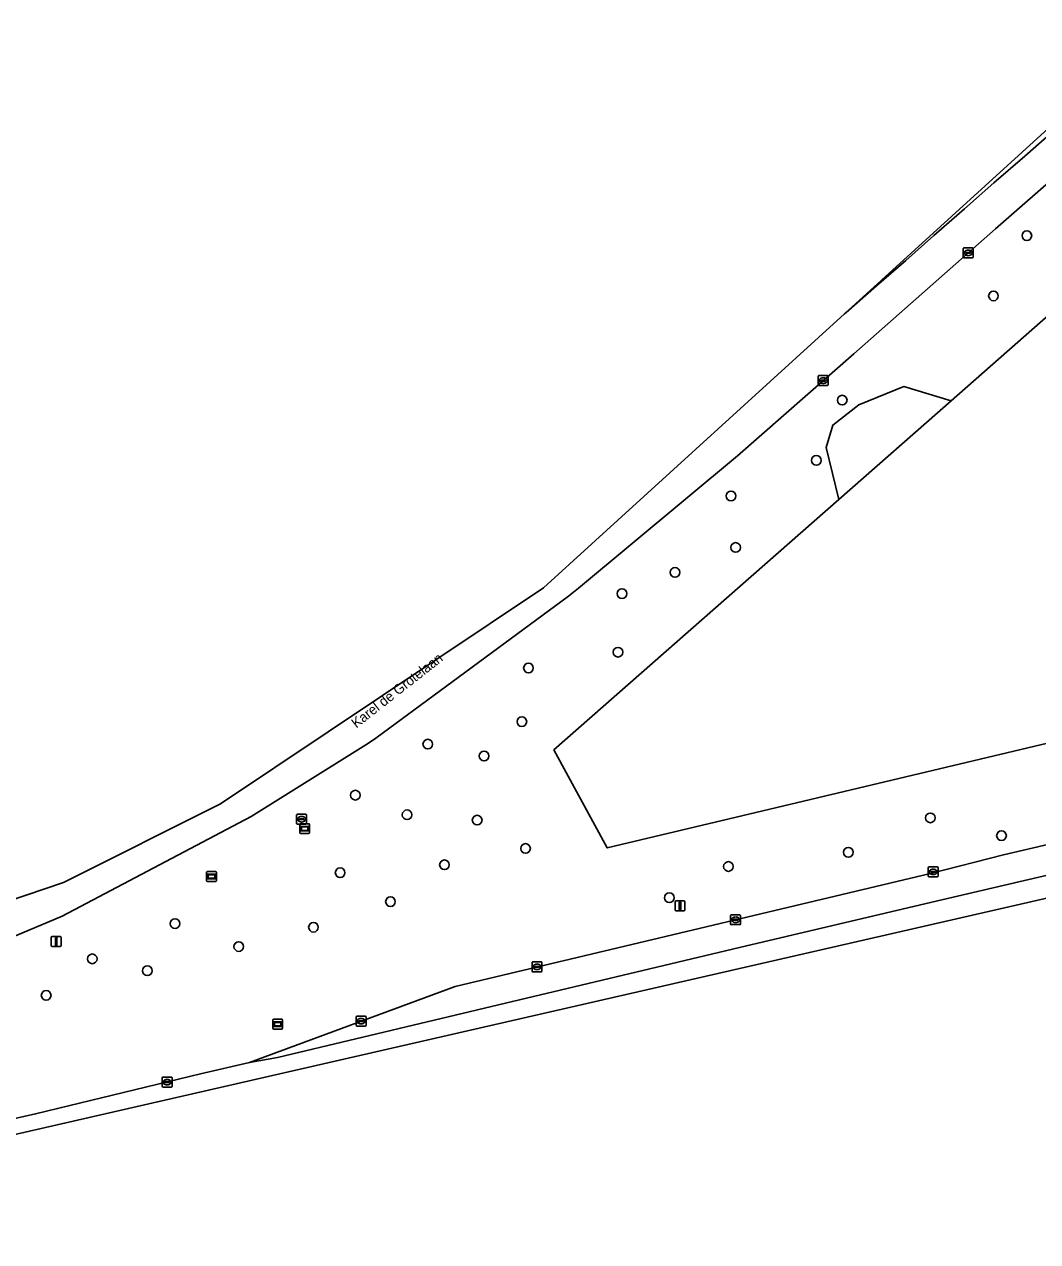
# Model space of a CAD drawing. Extents: x 158031 to 159244, y 380104 to 381214.
# Drawn here: x 158174 to 158276.2, y 380889.1 to 381011.9 of the extents above; entities that cross this region are included whole.
import ezdxf

# ---------------------------------------------------------------- set-up
doc = ezdxf.new("R2010")
doc.units = 0
for name, color, linetype in [('IMGEO_Afsluitpaal', 7, 'Continuous'), ('IMGEO_Berm_groen', 7, 'Continuous'), ('IMGEO_Boom', 7, 'Continuous'), ('IMGEO_Brandkraan', 7, 'Continuous'), ('IMGEO_Groenvoorziening', 7, 'Continuous'), ('IMGEO_Hek', 7, 'Continuous'), ('IMGEO_Kolk', 7, 'Continuous'), ('IMGEO_Lichtmast', 7, 'Continuous'), ('IMGEO_Openbare_ruimte_label', 7, 'Continuous'), ('IMGEO_Reclamebord', 7, 'Continuous'), ('IMGEO_Rijbaan_regionaal_gesloten', 7, 'Continuous'), ('IMGEO_Verklikker', 7, 'Continuous'), ('IMGEO_Wegwijzer', 7, 'Continuous')]:
    doc.layers.add(name, color=color, linetype=linetype)

msp = doc.modelspace()

# ---------------------------------------------------------------- linework, layer by layer
at = {"layer": 'IMGEO_Afsluitpaal'}
for p, q in [((158176.68, 380918.97), (158176.68, 380919.77)), ((158176.68, 380919.77), (158176.68, 380918.97)), ((158176.78, 380919.87), (158177.57, 380919.87)), ((158177.57, 380919.87), (158176.78, 380919.87)), ((158177.67, 380919.77), (158177.67, 380918.97)), ((158177.67, 380918.97), (158177.67, 380919.77)), ((158177.57, 380918.87), (158176.78, 380918.87)), ((158176.78, 380918.87), (158177.57, 380918.87))]:
    msp.add_line(p, q, dxfattribs=at)
msp.add_lwpolyline([(158177.1, 380919.74), (158177.25, 380919.74), (158177.25, 380918.99), (158177.1, 380918.99), (158177.1, 380919.74)], dxfattribs=at)
for centre, start, end in [((158176.78, 380919.77), 90, 180), ((158176.78, 380919.77), 90, 180), ((158177.57, 380919.77), 0, 90), ((158177.57, 380919.77), 360, 90), ((158176.78, 380918.97), 180, 270), ((158176.78, 380918.97), 180, 270), ((158177.57, 380918.97), 270, 0), ((158177.57, 380918.97), 270, 0)]:
    msp.add_arc(centre, 0.1, start, end, dxfattribs=at)
at = {"layer": 'IMGEO_Berm_groen'}
for points in [[(158278.95, 380997.38), (158271.98, 380991.29), (158257.69, 380978.69), (158245.96, 380968.39), (158229.89, 380955.02), (158228.88, 380954.2), (158209.44, 380939.88), (158208.7, 380939.39), (158196.86, 380931.99), (158177.79, 380921.93), (158156.82, 380913.1)], [(158282.76, 380940.68), (158232.8, 380928.81), (158227.42, 380938.7), (158256.18, 380963.98), (158254.89, 380969.21), (158255.55, 380971.48), (158258.19, 380973.54), (158262.74, 380975.37), (158267.5, 380973.93), (158290.8, 380994.41)], [(158153.95, 380897.19), (158175.11, 380901.96), (158191.76, 380905.99), (158196.68, 380907.16), (158217.44, 380914.82), (158265.44, 380926.24), (158272.8, 380928.1), (158289.52, 380932.01)]]:
    msp.add_lwpolyline(points, dxfattribs=at)
msp.add_lwpolyline([(158302.5, 380971.41), (158305.03, 380972.27), (158300.07, 380986.49), (158296.29, 380985.17), (158290.8, 380994.41), (158267.5, 380973.93), (158256.18, 380963.98), (158227.42, 380938.7), (158232.8, 380928.81), (158282.76, 380940.68), (158298.66, 380944.46), (158309.2, 380946.97)], close=True, dxfattribs=at)
at = {"layer": 'IMGEO_Boom'}
for centre in [(158275.15, 380990.6), (158271.78, 380984.52), (158256.51, 380974), (158253.9, 380967.92), (158245.29, 380964.33), (158245.76, 380959.13), (158239.64, 380956.61), (158234.29, 380954.47), (158233.89, 380948.56), (158224.85, 380946.96), (158224.18, 380941.55), (158214.69, 380939.28), (158220.37, 380938.08), (158207.38, 380934.13), (158212.6, 380932.15), (158219.67, 380931.61), (158265.41, 380931.84), (158272.59, 380930.05), (158224.55, 380928.75), (158257.13, 380928.36), (158205.84, 380926.3), (158216.37, 380927.1), (158245.03, 380926.93), (158239.07, 380923.78), (158210.92, 380923.39), (158189.18, 380921.17), (158203.15, 380920.8), (158195.61, 380918.85), (158180.82, 380917.61), (158186.38, 380916.41), (158176.17, 380913.92)]:
    msp.add_circle(centre, 0.489, dxfattribs=at)
at = {"layer": 'IMGEO_Brandkraan'}
for p, q in [((158201.45, 380931.27), (158201.45, 380932.13)), ((158201.52, 380932.2), (158202.38, 380932.2)), ((158201.71, 380931.69), (158201.71, 380931.71)), ((158201.75, 380931.74), (158202.15, 380931.74)), ((158202.15, 380931.66), (158201.75, 380931.66)), ((158201.94, 380931.98), (158201.96, 380931.98)), ((158202.19, 380931.71), (158202.19, 380931.69)), ((158202.45, 380932.13), (158202.45, 380931.27)), ((158202.38, 380931.2), (158201.52, 380931.2)), ((158201.96, 380931.42), (158201.93, 380931.42))]:
    msp.add_line(p, q, dxfattribs=at)
for points in [[(158201.45, 380931.27), (158201.45, 380932.13)], [(158201.52, 380932.2), (158202.38, 380932.2)], [(158202.45, 380932.13), (158202.45, 380931.27)], [(158202.38, 380931.2), (158201.52, 380931.2)]]:
    msp.add_lwpolyline(points, dxfattribs=at)
for centre, radius, start, end in [((158201.53, 380932.12), 0.0765, 91.552, 178.448), ((158201.53, 380932.12), 0.0765, 91.552, 178.448), ((158201.75, 380931.7), 0.0403, 85.8775, 175.7526), ((158201.74, 380931.69), 0.0366, 178.938, 274.7102), ((158202.15, 380931.7), 0.0386, 1.7309, 96.639), ((158202.15, 380931.7), 0.043, 264.8664, 352.4533), ((158202.37, 380932.12), 0.0765, 1.552, 88.448), ((158202.37, 380932.12), 0.0765, 1.552, 88.448), ((158201.53, 380931.28), 0.0765, 181.552, 268.448), ((158201.53, 380931.28), 0.0765, 181.552, 268.448), ((158202.37, 380931.28), 0.0765, 271.552, 358.448), ((158202.37, 380931.28), 0.0765, 271.552, 358.448)]:
    msp.add_arc(centre, radius, start, end, dxfattribs=at)
for centre, major_axis, ratio, start_param, end_param in [((158201.94, 380931.7), (-0.387, 0.002), 0.722429, 4.712389, 7.853982), ((158201.96, 380931.7), (-0.39, 0.002), 0.717154, 1.570796, 4.712389)]:
    msp.add_ellipse(centre, major_axis=major_axis, ratio=ratio, start_param=start_param, end_param=end_param, dxfattribs=at)
at = {"layer": 'IMGEO_Groenvoorziening'}
msp.add_lwpolyline([(158267.5, 380973.93), (158262.74, 380975.37), (158258.19, 380973.54), (158255.55, 380971.48), (158254.89, 380969.21), (158256.18, 380963.98)], close=True, dxfattribs=at)
at = {"layer": 'IMGEO_Hek'}
msp.add_lwpolyline([(158298.66, 380944.46), (158282.76, 380940.68), (158232.8, 380928.81), (158227.42, 380938.7), (158256.18, 380963.98), (158267.5, 380973.93), (158290.8, 380994.41)], dxfattribs=at)
at = {"layer": 'IMGEO_Kolk'}
for p, q in [((158268.73, 380988.44), (158268.73, 380989.29)), ((158268.8, 380989.36), (158269.66, 380989.36)), ((158269.66, 380988.36), (158268.8, 380988.36)), ((158268.99, 380988.86), (158268.99, 380988.87)), ((158269.03, 380988.91), (158269.43, 380988.91)), ((158269.43, 380988.82), (158269.03, 380988.82)), ((158269.24, 380988.58), (158269.21, 380988.58)), ((158269.22, 380989.14), (158269.24, 380989.14)), ((158269.47, 380988.87), (158269.47, 380988.86)), ((158269.73, 380989.29), (158269.73, 380988.44)), ((158254.1, 380975.55), (158254.1, 380976.4)), ((158254.17, 380976.47), (158255.03, 380976.47)), ((158254.36, 380975.97), (158254.36, 380975.98)), ((158254.4, 380976.02), (158254.8, 380976.02)), ((158254.79, 380975.93), (158254.4, 380975.93)), ((158254.59, 380976.25), (158254.61, 380976.25)), ((158254.84, 380975.98), (158254.84, 380975.97)), ((158255.1, 380976.4), (158255.1, 380975.55)), ((158255.03, 380975.47), (158254.17, 380975.47)), ((158254.61, 380975.69), (158254.58, 380975.69)), ((158265.19, 380925.96), (158265.19, 380926.82)), ((158265.27, 380926.89), (158266.12, 380926.89)), ((158266.19, 380926.82), (158266.19, 380925.96)), ((158266.12, 380925.89), (158265.27, 380925.89)), ((158265.45, 380926.38), (158265.45, 380926.4)), ((158265.49, 380926.43), (158265.89, 380926.43)), ((158265.89, 380926.35), (158265.49, 380926.35)), ((158265.68, 380926.67), (158265.71, 380926.67)), ((158265.7, 380926.11), (158265.68, 380926.11)), ((158265.94, 380926.4), (158265.94, 380926.38)), ((158245.25, 380921.13), (158245.25, 380921.98)), ((158245.32, 380922.06), (158246.18, 380922.06)), ((158245.74, 380921.84), (158245.76, 380921.84)), ((158246.25, 380921.98), (158246.25, 380921.13)), ((158246.18, 380921.06), (158245.32, 380921.06)), ((158245.51, 380921.55), (158245.51, 380921.56)), ((158245.55, 380921.6), (158245.95, 380921.6)), ((158245.94, 380921.51), (158245.55, 380921.51)), ((158245.76, 380921.28), (158245.73, 380921.28)), ((158245.99, 380921.56), (158245.99, 380921.55)), ((158225.21, 380916.37), (158225.21, 380917.23)), ((158225.28, 380917.3), (158226.14, 380917.3)), ((158225.7, 380917.08), (158225.72, 380917.08)), ((158226.21, 380917.23), (158226.21, 380916.37)), ((158226.14, 380916.3), (158225.28, 380916.3)), ((158225.47, 380916.79), (158225.47, 380916.81)), ((158225.51, 380916.84), (158225.91, 380916.84)), ((158225.91, 380916.76), (158225.51, 380916.76)), ((158225.72, 380916.52), (158225.69, 380916.52)), ((158225.95, 380916.81), (158225.95, 380916.79)), ((158207.46, 380910.89), (158207.46, 380911.75)), ((158207.53, 380911.82), (158208.38, 380911.82)), ((158208.38, 380910.82), (158207.53, 380910.82)), ((158207.71, 380911.31), (158207.71, 380911.33)), ((158208.15, 380911.28), (158207.75, 380911.28)), ((158207.76, 380911.36), (158208.15, 380911.36)), ((158207.94, 380911.6), (158207.97, 380911.6)), ((158207.97, 380911.04), (158207.94, 380911.04)), ((158208.2, 380911.33), (158208.2, 380911.31)), ((158208.46, 380911.75), (158208.46, 380910.89)), ((158187.88, 380904.75), (158187.88, 380905.6)), ((158187.95, 380905.67), (158188.81, 380905.67)), ((158188.81, 380904.67), (158187.95, 380904.67)), ((158188.14, 380905.17), (158188.14, 380905.18)), ((158188.18, 380905.22), (158188.58, 380905.22)), ((158188.57, 380905.13), (158188.18, 380905.13)), ((158188.39, 380904.89), (158188.36, 380904.89)), ((158188.37, 380905.45), (158188.39, 380905.45)), ((158188.62, 380905.18), (158188.62, 380905.17)), ((158188.88, 380905.6), (158188.88, 380904.75))]:
    msp.add_line(p, q, dxfattribs=at)
for points in [[(158268.73, 380988.44), (158268.73, 380989.29)], [(158268.8, 380989.36), (158269.66, 380989.36)], [(158269.66, 380988.36), (158268.8, 380988.36)], [(158269.73, 380989.29), (158269.73, 380988.44)], [(158254.1, 380975.55), (158254.1, 380976.4)], [(158254.17, 380976.47), (158255.03, 380976.47)], [(158255.1, 380976.4), (158255.1, 380975.55)], [(158255.03, 380975.47), (158254.17, 380975.47)], [(158265.19, 380925.96), (158265.19, 380926.82)], [(158265.27, 380926.89), (158266.12, 380926.89)], [(158266.19, 380926.82), (158266.19, 380925.96)], [(158266.12, 380925.89), (158265.27, 380925.89)], [(158245.25, 380921.13), (158245.25, 380921.98)], [(158245.32, 380922.06), (158246.18, 380922.06)], [(158246.25, 380921.98), (158246.25, 380921.13)], [(158246.18, 380921.06), (158245.32, 380921.06)], [(158225.21, 380916.37), (158225.21, 380917.23)], [(158225.28, 380917.3), (158226.14, 380917.3)], [(158226.21, 380917.23), (158226.21, 380916.37)], [(158226.14, 380916.3), (158225.28, 380916.3)], [(158207.46, 380910.89), (158207.46, 380911.75)], [(158207.53, 380911.82), (158208.38, 380911.82)], [(158208.38, 380910.82), (158207.53, 380910.82)], [(158208.46, 380911.75), (158208.46, 380910.89)], [(158187.88, 380904.75), (158187.88, 380905.6)], [(158187.95, 380905.67), (158188.81, 380905.67)], [(158188.81, 380904.67), (158187.95, 380904.67)], [(158188.88, 380905.6), (158188.88, 380904.75)]]:
    msp.add_lwpolyline(points, dxfattribs=at)
for centre, radius, start, end in [((158268.81, 380989.29), 0.0765, 91.552, 178.448), ((158268.81, 380989.29), 0.0765, 91.552, 178.448), ((158268.81, 380988.44), 0.0765, 181.552, 268.448), ((158268.81, 380988.44), 0.0765, 181.552, 268.448), ((158269.03, 380988.87), 0.0403, 85.8775, 175.7526), ((158269.02, 380988.86), 0.0366, 178.938, 274.7102), ((158269.43, 380988.87), 0.0386, 1.7309, 96.639), ((158269.43, 380988.86), 0.043, 264.8664, 352.4533), ((158269.65, 380989.29), 0.0765, 1.552, 88.448), ((158269.65, 380989.29), 0.0765, 1.552, 88.448), ((158269.65, 380988.44), 0.0765, 271.552, 358.448), ((158269.65, 380988.44), 0.0765, 271.552, 358.448), ((158254.17, 380976.4), 0.0765, 91.552, 178.448), ((158254.17, 380976.4), 0.0765, 91.552, 178.448), ((158254.4, 380975.98), 0.0403, 85.8775, 175.7526), ((158254.39, 380975.97), 0.0366, 178.938, 274.7102), ((158254.8, 380975.97), 0.043, 264.8664, 352.4533), ((158254.8, 380975.98), 0.0386, 1.7309, 96.639), ((158255.02, 380976.4), 0.0765, 1.552, 88.448), ((158255.02, 380976.4), 0.0765, 1.552, 88.448), ((158254.17, 380975.55), 0.0765, 181.552, 268.448), ((158254.17, 380975.55), 0.0765, 181.552, 268.448), ((158255.02, 380975.55), 0.0765, 271.552, 358.448), ((158255.02, 380975.55), 0.0765, 271.552, 358.448), ((158265.27, 380926.81), 0.0765, 91.552, 178.448), ((158265.27, 380926.81), 0.0765, 91.552, 178.448), ((158266.12, 380926.81), 0.0765, 1.552, 88.448), ((158266.12, 380926.81), 0.0765, 1.552, 88.448), ((158265.27, 380925.96), 0.0765, 181.552, 268.448), ((158265.27, 380925.96), 0.0765, 181.552, 268.448), ((158265.49, 380926.39), 0.0403, 85.8775, 175.7526), ((158265.49, 380926.38), 0.0366, 178.938, 274.7102), ((158265.9, 380926.39), 0.0386, 1.7309, 96.639), ((158265.89, 380926.39), 0.043, 264.8664, 352.4533), ((158266.12, 380925.96), 0.0765, 271.552, 358.448), ((158266.12, 380925.96), 0.0765, 271.552, 358.448), ((158245.32, 380921.98), 0.0765, 91.552, 178.448), ((158245.32, 380921.98), 0.0765, 91.552, 178.448), ((158246.17, 380921.98), 0.0765, 1.552, 88.448), ((158246.17, 380921.98), 0.0765, 1.552, 88.448), ((158245.32, 380921.13), 0.0765, 181.552, 268.448), ((158245.32, 380921.13), 0.0765, 181.552, 268.448), ((158245.55, 380921.56), 0.0403, 85.8775, 175.7526), ((158245.54, 380921.55), 0.0366, 178.938, 274.7102), ((158245.95, 380921.56), 0.043, 264.8664, 352.4533), ((158245.95, 380921.56), 0.0386, 1.7309, 96.639), ((158246.17, 380921.13), 0.0765, 271.552, 358.448), ((158246.17, 380921.13), 0.0765, 271.552, 358.448), ((158225.29, 380917.22), 0.0765, 91.552, 178.448), ((158225.29, 380917.22), 0.0765, 91.552, 178.448), ((158226.13, 380917.22), 0.0765, 1.552, 88.448), ((158226.13, 380917.22), 0.0765, 1.552, 88.448), ((158225.29, 380916.37), 0.0765, 181.552, 268.448), ((158225.29, 380916.37), 0.0765, 181.552, 268.448), ((158225.51, 380916.8), 0.0403, 85.8775, 175.7526), ((158225.5, 380916.79), 0.0366, 178.938, 274.7102), ((158225.91, 380916.8), 0.0386, 1.7309, 96.639), ((158225.91, 380916.8), 0.043, 264.8664, 352.4533), ((158226.13, 380916.37), 0.0765, 271.552, 358.448), ((158226.13, 380916.37), 0.0765, 271.552, 358.448), ((158207.53, 380911.74), 0.0765, 91.552, 178.448), ((158207.53, 380911.74), 0.0765, 91.552, 178.448), ((158207.53, 380910.9), 0.0765, 181.552, 268.448), ((158207.53, 380910.9), 0.0765, 181.552, 268.448), ((158207.75, 380911.32), 0.0403, 85.8775, 175.7526), ((158207.75, 380911.31), 0.0366, 178.938, 274.7102), ((158208.16, 380911.32), 0.0386, 1.7309, 96.639), ((158208.16, 380911.32), 0.043, 264.8664, 352.4533), ((158208.38, 380911.74), 0.0765, 1.552, 88.448), ((158208.38, 380911.74), 0.0765, 1.552, 88.448), ((158208.38, 380910.9), 0.0765, 271.552, 358.448), ((158208.38, 380910.9), 0.0765, 271.552, 358.448), ((158187.95, 380905.6), 0.0765, 91.552, 178.448), ((158187.95, 380905.6), 0.0765, 91.552, 178.448), ((158187.95, 380904.75), 0.0765, 181.552, 268.448), ((158187.95, 380904.75), 0.0765, 181.552, 268.448), ((158188.18, 380905.18), 0.0403, 85.8775, 175.7526), ((158188.17, 380905.17), 0.0366, 178.938, 274.7102), ((158188.58, 380905.17), 0.043, 264.8664, 352.4533), ((158188.58, 380905.18), 0.0386, 1.7309, 96.639), ((158188.8, 380905.6), 0.0765, 1.552, 88.448), ((158188.8, 380905.6), 0.0765, 1.552, 88.448), ((158188.8, 380904.75), 0.0765, 271.552, 358.448), ((158188.8, 380904.75), 0.0765, 271.552, 358.448)]:
    msp.add_arc(centre, radius, start, end, dxfattribs=at)
for centre, major_axis, ratio, start_param, end_param in [((158269.22, 380988.86), (-0.387, 0.002), 0.722429, 4.712389, 7.853982), ((158269.24, 380988.86), (-0.39, 0.002), 0.717154, 1.570796, 4.712389), ((158254.59, 380975.97), (-0.387, 0.002), 0.722429, 4.712389, 7.853982), ((158254.61, 380975.97), (-0.39, 0.002), 0.717154, 1.570796, 4.712389), ((158265.68, 380926.39), (-0.387, 0.002), 0.722429, 4.712389, 7.853982), ((158265.7, 380926.39), (-0.39, 0.002), 0.717154, 1.570796, 4.712389), ((158245.74, 380921.56), (-0.387, 0.002), 0.722429, 4.712389, 7.853982), ((158245.76, 380921.56), (-0.39, 0.002), 0.717154, 1.570796, 4.712389), ((158225.7, 380916.8), (-0.387, 0.002), 0.722429, 4.712389, 7.853982), ((158225.72, 380916.8), (-0.39, 0.002), 0.717154, 1.570796, 4.712389), ((158207.94, 380911.32), (-0.387, 0.002), 0.722429, 4.712389, 7.853982), ((158207.97, 380911.32), (-0.39, 0.002), 0.717154, 1.570796, 4.712389), ((158188.37, 380905.17), (-0.387, 0.002), 0.722429, 4.712389, 7.853982), ((158188.39, 380905.17), (-0.39, 0.002), 0.717154, 1.570796, 4.712389)]:
    msp.add_ellipse(centre, major_axis=major_axis, ratio=ratio, start_param=start_param, end_param=end_param, dxfattribs=at)
at = {"layer": 'IMGEO_Lichtmast'}
for p, q in [((158239.65, 380922.56), (158239.65, 380923.36)), ((158239.65, 380923.36), (158239.65, 380922.56)), ((158239.75, 380923.46), (158240.54, 380923.46)), ((158240.54, 380923.46), (158239.75, 380923.46)), ((158240.64, 380923.36), (158240.64, 380922.56)), ((158240.64, 380922.56), (158240.64, 380923.36)), ((158240.54, 380922.46), (158239.75, 380922.46)), ((158239.75, 380922.46), (158240.54, 380922.46))]:
    msp.add_line(p, q, dxfattribs=at)
msp.add_lwpolyline([(158240.07, 380923.33), (158240.22, 380923.33), (158240.22, 380922.58), (158240.07, 380922.58), (158240.07, 380923.33)], dxfattribs=at)
for centre, start, end in [((158239.75, 380923.36), 90, 180), ((158239.75, 380923.36), 90, 180), ((158240.54, 380923.36), 0, 90), ((158240.54, 380923.36), 360, 90), ((158239.75, 380922.56), 180, 270), ((158239.75, 380922.56), 180, 270), ((158240.54, 380922.56), 270, 0), ((158240.54, 380922.56), 270, 0)]:
    msp.add_arc(centre, 0.1, start, end, dxfattribs=at)
at = {"layer": 'IMGEO_Reclamebord'}
for p, q in [((158199.04, 380910.62), (158199.04, 380911.42)), ((158199.04, 380911.42), (158199.04, 380910.62)), ((158199.14, 380911.52), (158199.93, 380911.52)), ((158199.93, 380911.52), (158199.14, 380911.52)), ((158200.03, 380911.42), (158200.03, 380910.62)), ((158200.03, 380910.62), (158200.03, 380911.42)), ((158199.93, 380910.52), (158199.14, 380910.52)), ((158199.14, 380910.52), (158199.93, 380910.52))]:
    msp.add_line(p, q, dxfattribs=at)
for points in [[(158199.14, 380911.25), (158199.93, 380911.25), (158199.93, 380910.78), (158199.14, 380910.78), (158199.14, 380911.25)], [(158199.21, 380911.18), (158199.21, 380910.85), (158199.87, 380910.85), (158199.87, 380911.18), (158199.21, 380911.18)]]:
    msp.add_lwpolyline(points, dxfattribs=at)
for centre, start, end in [((158199.14, 380911.42), 90, 180), ((158199.14, 380911.42), 90, 180), ((158199.93, 380911.42), 0, 90), ((158199.93, 380911.42), 360, 90), ((158199.14, 380910.62), 180, 270), ((158199.14, 380910.62), 180, 270), ((158199.93, 380910.62), 270, 0), ((158199.93, 380910.62), 270, 0)]:
    msp.add_arc(centre, 0.1, start, end, dxfattribs=at)
at = {"layer": 'IMGEO_Rijbaan_regionaal_gesloten'}
for points in [[(158288.88, 381011.93), (158256.76, 380982.7), (158256.92, 380982.84), (158259.99, 380985.55), (158262.93, 380988.11), (158265.75, 380990.6), (158268.84, 380993.32), (158271.81, 380995.93), (158274.94, 380998.63), (158277.99, 381001.3), (158281.05, 381003.98), (158283.98, 381006.58), (158289.36, 381011.35), (158288.88, 381011.93)], [(158277.99, 381001.3), (158274.94, 380998.63), (158271.81, 380995.93), (158268.84, 380993.32), (158265.75, 380990.6), (158262.93, 380988.11), (158259.99, 380985.55), (158256.92, 380982.84), (158256.76, 380982.7), (158226.38, 380955.05), (158193.76, 380933.26), (158177.91, 380925.33), (158172.26, 380923.41)], [(158156.82, 380913.1), (158177.79, 380921.93), (158196.86, 380931.99), (158208.7, 380939.39), (158209.44, 380939.88), (158228.88, 380954.2), (158229.89, 380955.02), (158245.96, 380968.39), (158257.69, 380978.69), (158271.98, 380991.29), (158278.95, 380997.38)], [(158125.83, 380889.07), (158322.67, 380934.15)], [(158285.13, 380927.91), (158265.56, 380923.33), (158246.16, 380918.76), (158223.23, 380913.32), (158199.53, 380907.66), (158196.68, 380907.16), (158191.76, 380905.99), (158175.11, 380901.96), (158153.95, 380897.19)]]:
    msp.add_lwpolyline(points, dxfattribs=at)
msp.add_lwpolyline([(158319.75, 380936.01), (158322.06, 380936.57), (158321.97, 380936.95), (158321.27, 380939.76), (158320.04, 380939.45), (158312.81, 380937.72), (158298.93, 380934.3), (158294.52, 380933.23), (158293.11, 380932.87), (158291.69, 380932.52), (158289.52, 380932.01), (158272.8, 380928.1), (158265.44, 380926.24), (158217.44, 380914.82), (158196.68, 380907.16), (158199.53, 380907.66), (158223.23, 380913.32), (158246.16, 380918.76), (158265.56, 380923.33), (158285.13, 380927.91), (158304.58, 380932.47)], close=True, dxfattribs=at)
at = {"layer": 'IMGEO_Verklikker'}
for p, q in [((158201.77, 380930.35), (158201.77, 380931.15)), ((158201.77, 380931.15), (158201.77, 380930.35)), ((158201.87, 380931.25), (158202.66, 380931.25)), ((158202.66, 380931.25), (158201.87, 380931.25)), ((158202.76, 380931.15), (158202.76, 380930.35)), ((158202.76, 380930.35), (158202.76, 380931.15)), ((158202.66, 380930.25), (158201.87, 380930.25)), ((158201.87, 380930.25), (158202.66, 380930.25))]:
    msp.add_line(p, q, dxfattribs=at)
for points in [[(158201.87, 380930.98), (158202.65, 380930.98), (158202.65, 380930.52), (158201.87, 380930.52), (158201.87, 380930.98)], [(158201.93, 380930.92), (158201.93, 380930.58), (158202.59, 380930.58), (158202.59, 380930.92), (158201.93, 380930.92)]]:
    msp.add_lwpolyline(points, dxfattribs=at)
for centre, start, end in [((158201.87, 380931.15), 90, 180), ((158201.87, 380931.15), 90, 180), ((158202.66, 380931.15), 0, 90), ((158202.66, 380931.15), 360, 90), ((158201.87, 380930.35), 180, 270), ((158201.87, 380930.35), 180, 270), ((158202.66, 380930.35), 270, 0), ((158202.66, 380930.35), 270, 0)]:
    msp.add_arc(centre, 0.1, start, end, dxfattribs=at)
at = {"layer": 'IMGEO_Wegwijzer'}
for p, q in [((158192.36, 380925.51), (158192.36, 380926.31)), ((158192.36, 380926.31), (158192.36, 380925.51)), ((158192.46, 380926.41), (158193.25, 380926.41)), ((158193.25, 380926.41), (158192.46, 380926.41)), ((158193.35, 380926.31), (158193.35, 380925.51)), ((158193.35, 380925.51), (158193.35, 380926.31)), ((158193.25, 380925.41), (158192.46, 380925.41)), ((158192.46, 380925.41), (158193.25, 380925.41))]:
    msp.add_line(p, q, dxfattribs=at)
for points in [[(158192.46, 380926.14), (158193.25, 380926.14), (158193.25, 380925.68), (158192.46, 380925.68), (158192.46, 380926.14)], [(158192.52, 380926.08), (158192.52, 380925.74), (158193.18, 380925.74), (158193.18, 380926.08), (158192.52, 380926.08)]]:
    msp.add_lwpolyline(points, dxfattribs=at)
for centre, start, end in [((158192.46, 380926.31), 90, 180), ((158192.46, 380926.31), 90, 180), ((158192.46, 380925.51), 180, 270), ((158192.46, 380925.51), 180, 270), ((158193.25, 380926.31), 0, 90), ((158193.25, 380926.31), 360, 90), ((158193.25, 380925.51), 270, 0), ((158193.25, 380925.51), 270, 0)]:
    msp.add_arc(centre, 0.1, start, end, dxfattribs=at)

# ---------------------------------------------------------------- texts
at = {"layer": 'IMGEO_Openbare_ruimte_label'}
msp.add_text('Karel de Grotelaan', height=1, rotation=38.0961, dxfattribs=at).set_placement((158207.47, 380940.85))

doc.saveas('drawing.dxf')
